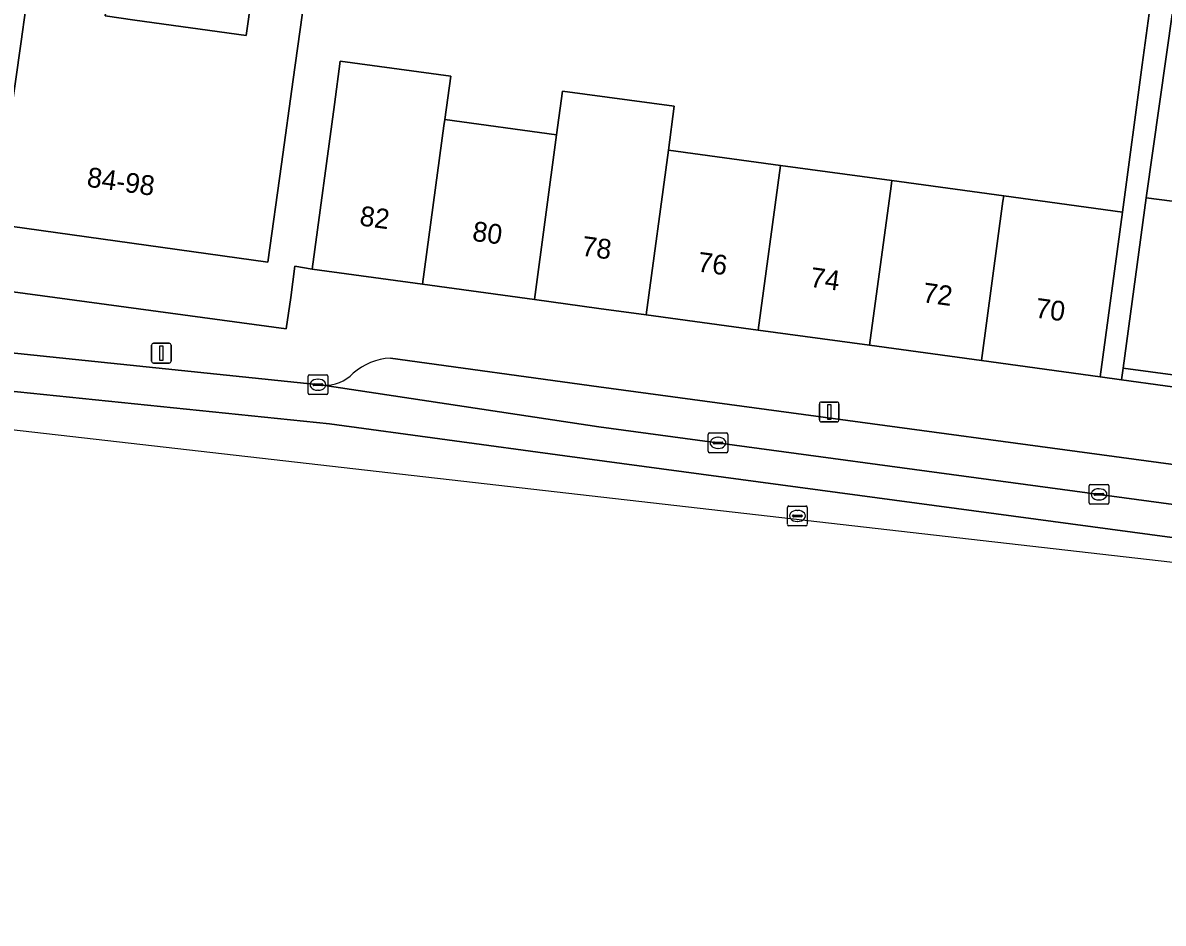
# Model space of a CAD drawing. Extents: x 159716 to 160783, y 383290 to 384031.
# Drawn here: x 160470.9 to 160528.5, y 383291.6 to 383337.1 of the extents above; entities that cross this region are included whole.
import ezdxf

# ---------------------------------------------------------------- set-up
doc = ezdxf.new("R2010")
doc.units = 0
for name, color, linetype in [('IMGEO_Erf', 7, 'Continuous'), ('IMGEO_Kolk', 7, 'Continuous'), ('IMGEO_Lichtmast', 7, 'Continuous'), ('IMGEO_Pand', 7, 'Continuous'), ('IMGEO_Pand_nummerreeks', 7, 'Continuous'), ('IMGEO_Parkeervlak_open', 7, 'Continuous'), ('IMGEO_Rijbaan_lokaal_gesloten', 7, 'Continuous'), ('IMGEO_Rijbaan_lokaal_open', 7, 'Continuous'), ('IMGEO_Rioolput', 7, 'Continuous'), ('IMGEO_Voetpad_open', 7, 'Continuous')]:
    doc.layers.add(name, color=color, linetype=linetype)

msp = doc.modelspace()

# ---------------------------------------------------------------- linework, layer by layer
at = {"layer": 'IMGEO_Erf'}
for points in [[(160475.686, 383341.966), (160475.059, 383337.469), (160476.551, 383337.261), (160482.192, 383336.474), (160482.742, 383340.419), (160485.367, 383340.053), (160484.56, 383334.256), (160483.963, 383329.977), (160483.273, 383325.024), (160469.525, 383326.939), (160470.215, 383331.892), (160470.814, 383336.177), (160471.698, 383342.522)], [(160526.498, 383319.668), (160526.418, 383319.087), (160530.83, 383318.479), (160530.902, 383319.083)]]:
    msp.add_lwpolyline(points, close=True, dxfattribs=at)
for points in [[(160529.68, 383342.542), (160527.656, 383328.281), (160530.821, 383327.876)], [(160439.143, 383327.741), (160472.517, 383323.239), (160484.208, 383321.662), (160484.44, 383323.248), (160484.638, 383324.819), (160485.516, 383324.669), (160486.641, 383332.992), (160486.937, 383335.185), (160492.53, 383334.43), (160492.225, 383332.23), (160497.872, 383331.459), (160498.171, 383333.667), (160503.819, 383332.904), (160503.52, 383330.689), (160509.186, 383329.916), (160514.812, 383329.148), (160520.466, 383328.377), (160526.464, 383327.559), (160527.469, 383334.991), (160527.972, 383338.718)]]:
    msp.add_lwpolyline(points, dxfattribs=at)
at = {"layer": 'IMGEO_Kolk'}
for p, q in [((160485.312, 383318.407), (160485.312, 383319.259)), ((160485.387, 383319.333), (160486.239, 383319.333)), ((160486.313, 383319.259), (160486.313, 383318.407)), ((160485.571, 383318.827), (160485.571, 383318.839)), ((160486.009, 383318.79), (160485.611, 383318.79)), ((160485.614, 383318.876), (160486.012, 383318.876)), ((160485.8, 383319.113), (160485.825, 383319.113)), ((160486.055, 383318.839), (160486.055, 383318.827)), ((160486.239, 383318.333), (160485.387, 383318.333)), ((160485.823, 383318.553), (160485.798, 383318.553)), ((160505.602, 383316.396), (160506.454, 383316.396)), ((160505.527, 383315.47), (160505.527, 383316.322)), ((160505.786, 383315.89), (160505.786, 383315.902)), ((160506.224, 383315.853), (160505.826, 383315.853)), ((160505.829, 383315.939), (160506.227, 383315.939)), ((160506.015, 383316.176), (160506.04, 383316.176)), ((160506.27, 383315.902), (160506.27, 383315.89)), ((160506.528, 383316.322), (160506.528, 383315.47)), ((160506.454, 383315.396), (160505.602, 383315.396)), ((160506.038, 383315.616), (160506.013, 383315.616)), ((160524.78, 383312.868), (160524.78, 383313.72)), ((160524.855, 383313.794), (160525.707, 383313.794)), ((160525.268, 383313.574), (160525.293, 383313.574)), ((160525.781, 383313.72), (160525.781, 383312.868)), ((160525.039, 383313.288), (160525.039, 383313.3)), ((160525.477, 383313.251), (160525.079, 383313.251)), ((160525.082, 383313.337), (160525.48, 383313.337)), ((160525.291, 383313.014), (160525.266, 383313.014)), ((160525.523, 383313.3), (160525.523, 383313.288)), ((160525.707, 383312.794), (160524.855, 383312.794))]:
    msp.add_line(p, q, dxfattribs=at)
for points in [[(160485.312, 383318.407), (160485.312, 383319.259)], [(160485.387, 383319.333), (160486.239, 383319.333)], [(160486.313, 383319.259), (160486.313, 383318.407)], [(160486.239, 383318.333), (160485.387, 383318.333)], [(160505.602, 383316.396), (160506.454, 383316.396)], [(160505.527, 383315.47), (160505.527, 383316.322)], [(160506.528, 383316.322), (160506.528, 383315.47)], [(160506.454, 383315.396), (160505.602, 383315.396)], [(160524.78, 383312.868), (160524.78, 383313.72)], [(160524.855, 383313.794), (160525.707, 383313.794)], [(160525.781, 383313.72), (160525.781, 383312.868)], [(160525.707, 383312.794), (160524.855, 383312.794)]]:
    msp.add_lwpolyline(points, dxfattribs=at)
for centre, radius, start, end in [((160485.389, 383319.257), 0.0765, 91.55205, 178.44795), ((160485.389, 383319.257), 0.0765, 91.55205, 178.44795), ((160486.237, 383319.257), 0.0765, 1.55205, 88.44795), ((160486.237, 383319.257), 0.0765, 1.55205, 88.44795), ((160485.611, 383318.836), 0.0403, 85.87752, 175.75265), ((160485.608, 383318.826), 0.0366, 178.93798, 274.71019), ((160486.012, 383318.833), 0.043, 264.86636, 352.45326), ((160486.016, 383318.838), 0.0386, 1.73085, 96.63898), ((160485.389, 383318.409), 0.0765, 181.55205, 268.44795), ((160485.389, 383318.409), 0.0765, 181.55205, 268.44795), ((160486.237, 383318.409), 0.0765, 271.55205, 358.44795), ((160486.237, 383318.409), 0.0765, 271.55205, 358.44795), ((160505.604, 383316.32), 0.0765, 91.55205, 178.44795), ((160505.604, 383316.32), 0.0765, 91.55205, 178.44795), ((160506.452, 383316.32), 0.0765, 1.55205, 88.44795), ((160506.452, 383316.32), 0.0765, 1.55205, 88.44795), ((160505.826, 383315.899), 0.0403, 85.87752, 175.75265), ((160505.823, 383315.889), 0.0366, 178.93798, 274.71019), ((160506.227, 383315.896), 0.043, 264.86636, 352.45326), ((160506.231, 383315.901), 0.0386, 1.73085, 96.63898), ((160505.604, 383315.472), 0.0765, 181.55205, 268.44795), ((160505.604, 383315.472), 0.0765, 181.55205, 268.44795), ((160506.452, 383315.472), 0.0765, 271.55205, 358.44795), ((160506.452, 383315.472), 0.0765, 271.55205, 358.44795), ((160524.857, 383313.718), 0.0765, 91.55205, 178.44795), ((160524.857, 383313.718), 0.0765, 91.55205, 178.44795), ((160525.705, 383313.718), 0.0765, 1.55205, 88.44795), ((160525.705, 383313.718), 0.0765, 1.55205, 88.44795), ((160525.079, 383313.297), 0.0403, 85.87752, 175.75265), ((160525.076, 383313.287), 0.0366, 178.93798, 274.71019), ((160525.48, 383313.294), 0.043, 264.86636, 352.45326), ((160525.484, 383313.299), 0.0386, 1.73085, 96.63898), ((160524.857, 383312.87), 0.0765, 181.55205, 268.44795), ((160524.857, 383312.87), 0.0765, 181.55205, 268.44795), ((160525.705, 383312.87), 0.0765, 271.55205, 358.44795), ((160525.705, 383312.87), 0.0765, 271.55205, 358.44795)]:
    msp.add_arc(centre, radius, start, end, dxfattribs=at)
for centre, major_axis, ratio, start_param, end_param in [((160485.799, 383318.833), (-0.387, 0.002), 0.722429, 4.712389, 7.853982), ((160485.824, 383318.833), (-0.39, 0.002), 0.717154, 1.570796, 4.712389), ((160506.014, 383315.896), (-0.387, 0.002), 0.722429, 4.712389, 7.853982), ((160506.039, 383315.896), (-0.39, 0.002), 0.717154, 1.570796, 4.712389), ((160525.267, 383313.294), (-0.387, 0.002), 0.722429, 4.712389, 7.853982), ((160525.292, 383313.294), (-0.39, 0.002), 0.717154, 1.570796, 4.712389)]:
    msp.add_ellipse(centre, major_axis=major_axis, ratio=ratio, start_param=start_param, end_param=end_param, dxfattribs=at)
at = {"layer": 'IMGEO_Lichtmast'}
for p, q in [((160477.404, 383320.028), (160477.404, 383320.828)), ((160477.404, 383320.828), (160477.404, 383320.028)), ((160477.504, 383320.928), (160478.294, 383320.928)), ((160478.294, 383320.928), (160477.504, 383320.928)), ((160478.394, 383320.828), (160478.394, 383320.028)), ((160478.394, 383320.028), (160478.394, 383320.828)), ((160478.294, 383319.928), (160477.504, 383319.928)), ((160477.504, 383319.928), (160478.294, 383319.928)), ((160511.151, 383317.058), (160511.151, 383317.858)), ((160511.151, 383317.858), (160511.151, 383317.058)), ((160511.251, 383317.958), (160512.041, 383317.958)), ((160512.041, 383317.958), (160511.251, 383317.958)), ((160512.141, 383317.858), (160512.141, 383317.058)), ((160512.141, 383317.058), (160512.141, 383317.858)), ((160512.041, 383316.958), (160511.251, 383316.958)), ((160511.251, 383316.958), (160512.041, 383316.958))]:
    msp.add_line(p, q, dxfattribs=at)
for points in [[(160477.824, 383320.803), (160477.974, 383320.803), (160477.974, 383320.053), (160477.824, 383320.053), (160477.824, 383320.803)], [(160511.571, 383317.833), (160511.721, 383317.833), (160511.721, 383317.083), (160511.571, 383317.083), (160511.571, 383317.833)]]:
    msp.add_lwpolyline(points, dxfattribs=at)
for centre, start, end in [((160477.504, 383320.828), 90, 180), ((160477.504, 383320.828), 90, 180), ((160478.294, 383320.828), 0, 90), ((160478.294, 383320.828), 360, 90), ((160477.504, 383320.028), 180, 270), ((160477.504, 383320.028), 180, 270), ((160478.294, 383320.028), 270, 0), ((160478.294, 383320.028), 270, 0), ((160511.251, 383317.858), 90, 180), ((160511.251, 383317.858), 90, 180), ((160512.041, 383317.858), 0, 90), ((160512.041, 383317.858), 360, 90), ((160511.251, 383317.058), 180, 270), ((160511.251, 383317.058), 180, 270), ((160512.041, 383317.058), 270, 0), ((160512.041, 383317.058), 270, 0)]:
    msp.add_arc(centre, 0.1, start, end, dxfattribs=at)
at = {"layer": 'IMGEO_Pand'}
for points in [[(160485.367, 383340.053), (160482.742, 383340.419), (160482.192, 383336.474), (160476.551, 383337.261), (160475.059, 383337.469), (160475.686, 383341.966), (160471.698, 383342.522), (160470.814, 383336.177), (160470.215, 383331.892), (160469.525, 383326.939), (160483.273, 383325.024), (160483.963, 383329.977), (160484.56, 383334.256)], [(160491.099, 383323.907), (160492.181, 383331.915), (160492.225, 383332.23), (160492.53, 383334.43), (160486.937, 383335.185), (160486.641, 383332.992), (160485.516, 383324.669)], [(160497.872, 383331.459), (160496.747, 383323.137), (160500, 383322.693), (160502.395, 383322.366), (160503.52, 383330.689), (160503.819, 383332.904), (160498.171, 383333.667)], [(160497.872, 383331.459), (160492.225, 383332.23), (160492.181, 383331.915), (160491.099, 383323.907), (160496.747, 383323.137)], [(160502.395, 383322.366), (160508.061, 383321.593), (160509.186, 383329.916), (160503.52, 383330.689)], [(160514.812, 383329.148), (160509.186, 383329.916), (160508.061, 383321.593), (160513.69, 383320.825), (160514.776, 383328.862)], [(160519.338, 383320.055), (160520.425, 383328.1), (160520.466, 383328.377), (160514.812, 383329.148), (160514.776, 383328.862), (160513.69, 383320.825)], [(160531.846, 383318.34), (160533.253, 383328.76), (160530.98, 383329.065), (160530.821, 383327.876), (160527.656, 383328.281), (160526.498, 383319.668), (160530.902, 383319.083), (160530.83, 383318.479)], [(160519.338, 383320.055), (160525.339, 383319.236), (160526.464, 383327.559), (160520.466, 383328.377), (160520.425, 383328.1)]]:
    msp.add_lwpolyline(points, close=True, dxfattribs=at)
at = {"layer": 'IMGEO_Parkeervlak_open'}
for points in [[(160574.767, 383308.623), (160500, 383318.727), (160489.476, 383320.182)], [(160486.062, 383318.807), (160500, 383316.709), (160577.778, 383306.197)]]:
    msp.add_lwpolyline(points, dxfattribs=at)
for centre, radius, start, end in [((160489.667, 383317.042), 3.146, 93.48185, 131.16801), ((160486.15, 383320.837), 2.032, 267.52921, 315.38938)]:
    msp.add_arc(centre, radius, start, end, dxfattribs=at)
at = {"layer": 'IMGEO_Rijbaan_lokaal_gesloten'}
for points in [[(160577.892, 383306.182), (160577.778, 383306.197), (160500, 383316.709), (160486.062, 383318.807), (160472.26, 383320.241), (160451.222, 383322.426), (160446.544, 383322.901), (160437.581, 383323.812), (160424.277, 383325.265), (160424.111, 383323.335), (160452.223, 383320.364), (160486.389, 383316.854), (160498.28, 383315.238), (160579.205, 383304.366), (160609.931, 383303.645), (160610.025, 383305.915)], [(160611.664, 383303.613), (160609.931, 383303.645), (160579.205, 383304.366), (160498.28, 383315.238), (160486.389, 383316.854), (160452.223, 383320.364), (160424.111, 383323.335), (160424.079, 383322.77), (160434.799, 383320.625), (160444.505, 383319.517), (160567.347, 383305.487), (160595.914, 383302.019), (160637.427, 383296.979), (160684.384, 383291.625)]]:
    msp.add_lwpolyline(points, dxfattribs=at)
at = {"layer": 'IMGEO_Rijbaan_lokaal_open'}
msp.add_lwpolyline([(160527.972, 383338.718), (160527.469, 383334.991), (160526.464, 383327.559), (160525.339, 383319.236), (160526.418, 383319.087), (160526.498, 383319.668), (160527.656, 383328.281), (160529.68, 383342.542)], dxfattribs=at)
at = {"layer": 'IMGEO_Rioolput'}
for p, q in [((160509.54, 383311.779), (160509.54, 383312.631)), ((160509.615, 383312.705), (160510.467, 383312.705)), ((160510.028, 383312.485), (160510.053, 383312.485)), ((160510.541, 383312.631), (160510.541, 383311.779)), ((160509.799, 383312.199), (160509.799, 383312.211)), ((160510.237, 383312.162), (160509.839, 383312.162)), ((160509.842, 383312.248), (160510.24, 383312.248)), ((160510.051, 383311.925), (160510.026, 383311.925)), ((160510.283, 383312.211), (160510.283, 383312.199)), ((160510.467, 383311.705), (160509.615, 383311.705))]:
    msp.add_line(p, q, dxfattribs=at)
for points in [[(160509.54, 383311.779), (160509.54, 383312.631)], [(160509.615, 383312.705), (160510.467, 383312.705)], [(160510.541, 383312.631), (160510.541, 383311.779)], [(160510.467, 383311.705), (160509.615, 383311.705)]]:
    msp.add_lwpolyline(points, dxfattribs=at)
for centre, radius, start, end in [((160509.617, 383312.629), 0.0765, 91.55205, 178.44795), ((160509.617, 383312.629), 0.0765, 91.55205, 178.44795), ((160510.465, 383312.629), 0.0765, 1.55205, 88.44795), ((160510.465, 383312.629), 0.0765, 1.55205, 88.44795), ((160509.617, 383311.781), 0.0765, 181.55205, 268.44795), ((160509.617, 383311.781), 0.0765, 181.55205, 268.44795), ((160509.839, 383312.208), 0.0403, 85.87752, 175.75265), ((160509.836, 383312.198), 0.0366, 178.93798, 274.71019), ((160510.24, 383312.205), 0.043, 264.86636, 352.45326), ((160510.244, 383312.21), 0.0386, 1.73085, 96.63898), ((160510.465, 383311.781), 0.0765, 271.55205, 358.44795), ((160510.465, 383311.781), 0.0765, 271.55205, 358.44795)]:
    msp.add_arc(centre, radius, start, end, dxfattribs=at)
for centre, major_axis, ratio, start_param, end_param in [((160510.027, 383312.205), (-0.387, 0.002), 0.722429, 4.712389, 7.853982), ((160510.052, 383312.205), (-0.39, 0.002), 0.717154, 1.570796, 4.712389)]:
    msp.add_ellipse(centre, major_axis=major_axis, ratio=ratio, start_param=start_param, end_param=end_param, dxfattribs=at)
at = {"layer": 'IMGEO_Voetpad_open'}
for points in [[(160472.517, 383323.239), (160439.143, 383327.741), (160439.121, 383327.59), (160427.813, 383329.12), (160426.574, 383329.386), (160418.497, 383331.122)], [(160424.277, 383325.265), (160437.581, 383323.812), (160437.731, 383325.116), (160451.353, 383323.657), (160451.222, 383322.426), (160472.26, 383320.241), (160486.062, 383318.807)], [(160530.83, 383318.479), (160526.418, 383319.087), (160525.339, 383319.236), (160519.338, 383320.055), (160513.69, 383320.825), (160508.061, 383321.593), (160502.395, 383322.366), (160500, 383322.693), (160496.747, 383323.137), (160491.099, 383323.907), (160485.516, 383324.669), (160484.638, 383324.819), (160484.44, 383323.248), (160484.208, 383321.662), (160472.517, 383323.239)], [(160489.476, 383320.182), (160500, 383318.727), (160574.767, 383308.623)]]:
    msp.add_lwpolyline(points, dxfattribs=at)
for centre, radius, start, end in [((160489.667, 383317.042), 3.146, 93.48185, 131.16801), ((160486.15, 383320.837), 2.032, 267.52921, 315.38938)]:
    msp.add_arc(centre, radius, start, end, dxfattribs=at)

# ---------------------------------------------------------------- texts
at = {"layer": 'IMGEO_Pand_nummerreeks'}
for s, rotation, p in [('84-98', 352.07026, (160474.098, 383328.847)), ('82', 352.23117, (160487.88, 383326.889)), ('80', 352.23117, (160493.575, 383326.113)), ('78', 352.22669, (160499.097, 383325.361)), ('76', 352.23117, (160504.95, 383324.561)), ('74', 352.23117, (160510.639, 383323.785)), ('72', 352.23117, (160516.325, 383323.009)), ('70', 352.23117, (160522.02, 383322.232))]:
    msp.add_text(s, height=1, rotation=rotation, dxfattribs=at).set_placement(p)

doc.saveas('drawing.dxf')
